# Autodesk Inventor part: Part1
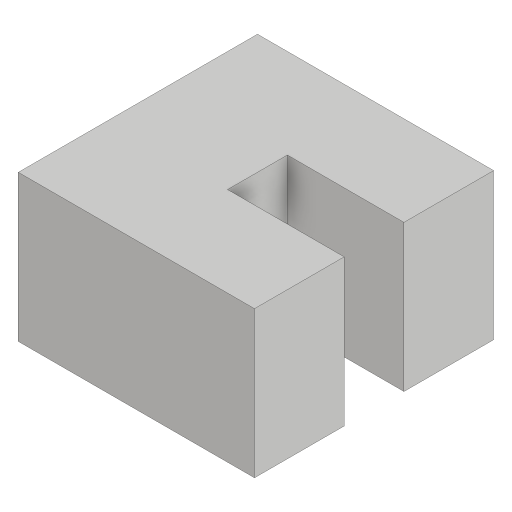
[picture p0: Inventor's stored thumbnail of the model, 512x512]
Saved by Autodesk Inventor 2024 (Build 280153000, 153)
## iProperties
Created: 2015-07
Part Number: Part1
Material: Generic
Document SubType Name: Modeling
Designer: Sandeep
Density: 1 g/cm^3
Appearance: Default
Author: Sandeep
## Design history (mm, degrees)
sketch "Sketch1"
  geometry: L1 (0, 0)-(-30, 0); L2 (-30, 0)-(-30, 40); L3 (-30, 40)-(0, 40); L4 (0, 40)-(0, 0)
  constraints: 8 end point, 2 parallel, 1 horizontal, 1 perpendicular
  dimensions: "d0" = 30 distance between parallel lines of L4 L2; "d1" = 40 distance of L1.end L2.end
extrude "Extrusion1" new body sketch "Sketch1" distance "d2" = 15; taper "d3" = 0 deg
sketch "Sketch2"
  geometry: L1 (0, 40)-(0, 0) reference; L2 (-15, 0)-(-15, 40) reference; L3 (0, 0)-(-15, 0) reference; L4 (-15, 15)-(0, 15); L5 (0, 15)-(0, 25); L6 (0, 25)-(-15, 25); L7 (-15, 25)-(-15, 15)
  constraints: 8 end point, 2 parallel, 2 point on line, 1 horizontal, 1 perpendicular
  dimensions: "d4" = 10 distance between parallel lines of L6 L4; "d5" = 15 distance between parallel lines of L3 L4
extrude "Extrusion2" cut sketch "Sketch2" distance "d6" = 10; taper "d7" = 0 deg
node "Direct Edit2"
body "Solid1"
feature "Size2" dims "d9" = 9.5
